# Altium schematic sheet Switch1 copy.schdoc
size 299 x 312 mm
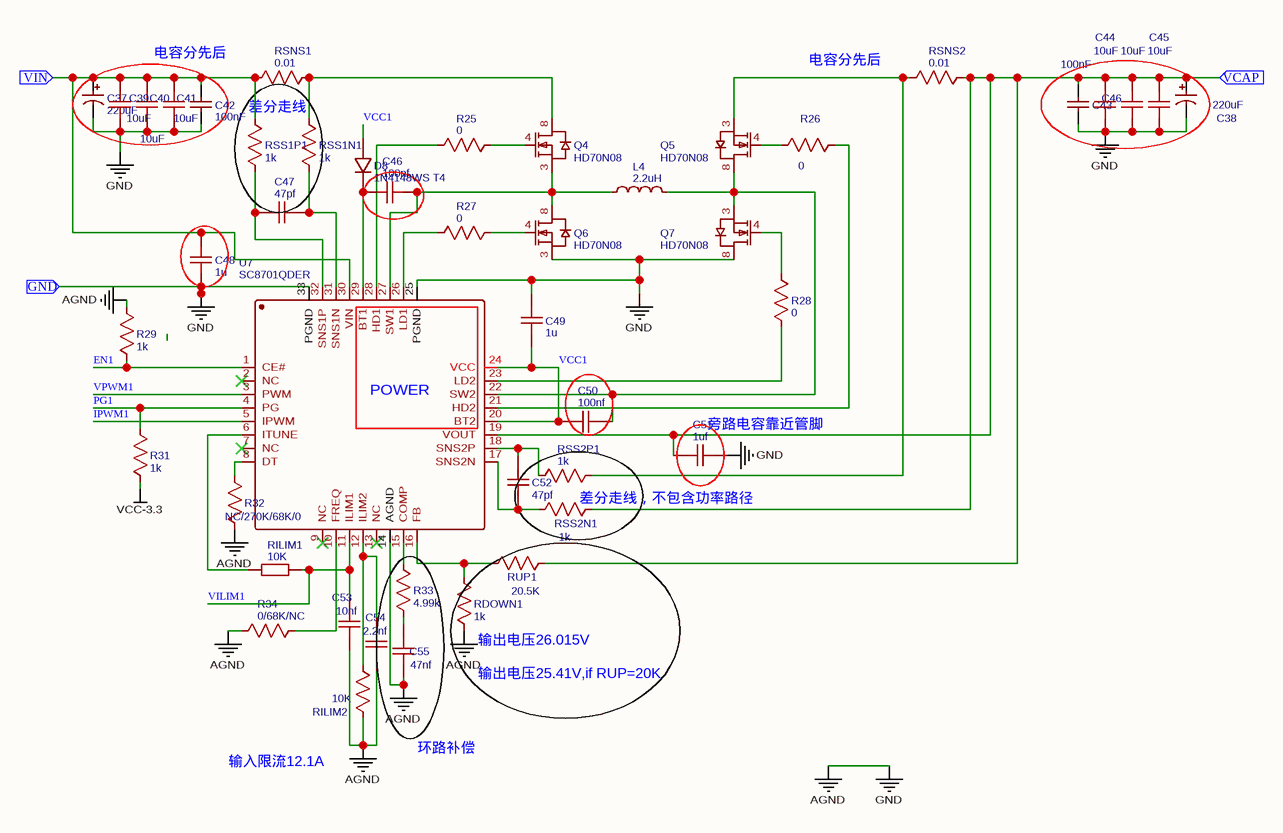
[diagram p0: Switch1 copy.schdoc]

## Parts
C37  220uF  [CAP-SMD_BD10.0-L10.3-W10.3-FD]
C38  220uF  [CAP-SMD_BD10.0-L10.3-W10.3-FD]
C39  10uF  [C1206]
C40  10uF  [C1206]
C41  10uF  [C1206]
C42  100nF  [C0603]
C43  100nF  [C0603]
C44  10uF  [C1206]
C45  10uF  [C1206]
C46  100nf  [C0402]
C47  47pf  [C0402]
C48  1u  [C0402]
C49  1u  [C0402]
C50  100nf  [C0402]
C51  1uf  [C0402]
C52  47pf  [C0402]
C53  10nf  [C0402]
C54  2.2nf  [C0402]
C55  47nf  [C0402]
D8  1N4148WS T4  [SOD-323_L1.8-W1.3-LS2.5-FD]
L4  2.2uH  [IND-SMD_L17.5-W17.0_YXMAC1770]
NO1  10uF  [C1206]
Q4  HD70N08  [PDFN-8_L4.9-W5.8-P1.27-LS6.1-BL FOR3]
Q5  HD70N08  [PDFN-8_L4.9-W5.8-P1.27-LS6.1-BL FOR3]
Q6  HD70N08  [PDFN-8_L4.9-W5.8-P1.27-LS6.1-BL FOR3]
Q7  HD70N08  [PDFN-8_L4.9-W5.8-P1.27-LS6.1-BL FOR3]
R25  0  [R0603]
R26  0  [R0603]
R27  0  [R0603]
R28  0  [R0603]
R29  1k  [R0402]
R31  1k  [R0402]
R32  NC/270K/68K/0  [R0402]
R33  4.99k  [R0402]
R34  0/68K/NC  [R0402]
RDOWN1  1k  [R0402]
RILIM1  10K  [R0402]
RILIM2  10K  [R0402]
RSNS1  0.01  [R0805]
RSNS2  0.01  [R0805]
RSS1N1  1k  [R0402]
RSS1P1  1k  [R0402]
RSS2N1  1k  [R0402]
RSS2P1  1k  [R0402]
RUP1  20.5K  [R0402]
U7  SC8701QDER  [QFN-32_L4.0-W4.0-P0.4-BL-EP2.6]

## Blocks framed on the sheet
POWER: U7

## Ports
GND (in), VCAP (in), VIN (in)

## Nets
AGND: C37.2 C38.2 C39.1 C40.1 C41.1 C42.1 C43.1 C44.1 C45.1 C48.1 C49.2 C51.1 C53.1 C54.1 C55.1 NO1.1 Q6.3(S) Q7.8(D) R29.2 R32.1 R34.1 RDOWN1.1 RILIM2.1 U7.14(AGND) U7.25(PGND) U7.33(PGND) ; port GND  [also labelled GND]
VCC-3.3: R31.1
EN1: R29.1 U7.1(CE#)
IPWM1: U7.5(IPWM)
PG1: R31.2 U7.4(PG)
VCAP: C38.1 C43.2 C44.2 C45.2 C51.2 NO1.2 RSNS2.2 RSS2N1.2 RUP1.2 U7.19(VOUT) ; port VCAP
VCC1: C49.1 C50.2 D8.1(A) U7.20(BT2) U7.24(VCC)
VILIM1: C53.2 RILIM1.2 U7.11(ILIM1)
VIN: C37.1 C39.2 C40.2 C41.2 C42.2 C48.2 RSNS1.1 RSS1P1.2 U7.30(VIN) ; port VIN
VPWM1: U7.3(PWM)
NetC46_1: C46.1 D8.2(K) U7.29(BT1)
NetC46_2: C46.2 L4.1 Q4.3(S) Q6.8(D) U7.27(SW1)
NetC47_1: C47.1 RSS1N1.1 U7.31(SNS1N)
NetC47_2: C47.2 RSS1P1.1 U7.32(SNS1P)
NetC50_1: C50.1 L4.2 Q5.8(D) Q7.3(S) U7.22(SW2)
NetC52_1: C52.1 RSS2P1.1 U7.18(SNS2P)
NetC52_2: C52.2 RSS2N1.1 U7.17(SNS2N)
NetC54_2: C54.2 RILIM2.2 U7.12(ILIM2)
NetC55_2: C55.2 R33.1
NetQ4_4: Q4.4(G) R25.2
NetQ4_8: Q4.8(D) RSNS1.2 RSS1N1.2
NetQ5_3: Q5.3(S) RSNS2.1 RSS2P1.2
NetQ5_4: Q5.4(G) R26.1
NetQ6_4: Q6.4(G) R27.2
NetQ7_4: Q7.4(G) R28.2
NetR25_1: R25.1 U7.28(HD1)
NetR26_2: R26.2 U7.21(HD2)
NetR27_1: R27.1 U7.26(LD1)
NetR28_1: R28.1 U7.23(LD2)
NetR32_2: R32.2 U7.8(DT)
NetR33_2: R33.2 U7.15(COMP)
NetR34_2: R34.2 U7.10(FREQ)
NetRDOWN1_2: RDOWN1.2 RUP1.1 U7.16(FB)
NetRILIM1_1: RILIM1.1 U7.6(ITUNE)

Not connected (* = marked no-connect by the designer): U7 2(NC)* 7(NC)* 9(NC)* 13(NC)*

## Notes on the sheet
- 电容分先后
- (near RSS1P1) 差分走线
- (near C44) C46
- (near C51) 旁路电容靠近管脚
- (near RSS2N1) 差分走线，不包含功率路径
- (near RDOWN1) 输出电压26.015V
- (near RDOWN1) 输出电压25.41V,if RUP=20K
- 输入限流12.1A
- 环路补偿

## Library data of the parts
C37 C38 = 220uF: BOM_Manufacturer: CapXon; BOM_Manufacturer Part: DV221M050G105A; nameAlias: Capacitance
C39-C41 C44 C45 NO1 = 10uF: BOM_Manufacturer: MuRata; BOM_Manufacturer Part: GRM31CR61H106KA12L; nameAlias: Capacitance
C42 C43 = 100nF: BOM_Manufacturer Part: CL10B104JB8NNNC; BOM_Manufacturer: SAMSUNG; nameAlias: Capacitance; SMT Type: Extend
C46 C50 = 100nf: nameAlias: Value(F)
C47 C52 = 47pf: nameAlias: Value(F)
C48 C49 = 1u: nameAlias: Value(F)
C51 = 1uf: nameAlias: Value(F)
C53 = 10nf: nameAlias: Value(F)
C54 = 2.2nf: nameAlias: Value(F)
C55 = 47nf: nameAlias: Value(F)
D8 = 1N4148WS T4: BOM_Manufacturer: CJ; SMT Type: Basic
L4 = 2.2uH: BOM_Manufacturer: YUXIN TECH; BOM_Manufacturer Part: YXMAC1770-2R2M-IGP; nameAlias: Inductance; Contributor: LCSC
Q4-Q7 = HD70N08: BOM_Manufacturer: HL; Contributor: LCSC
R25-R28 = 0: nameAlias: Value(Ω)
R29 R31 RDOWN1 RSS1N1 RSS1P1 RSS2N1 RSS2P1 = 1k: nameAlias: Value(Ω)
R32 = NC/270K/68K/0: nameAlias: Value(Ω)
R33 = 4.99k: nameAlias: Value(Ω)
R34 = 0/68K/NC: nameAlias: Value(Ω)
RILIM1 = 10K: nameAlias: Resistance (Ohms); Contributor: LCSC
RILIM2 = 10K: nameAlias: Value(Ω)
RSNS1 RSNS2 = 0.01: nameAlias: Value(Ω)
RUP1 = 20.5K: nameAlias: Value(Ω)
U7 = SC8701QDER: BOM_Manufacturer: Southchip Semicon; Contributor: LCSC; SMT Type: Extend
